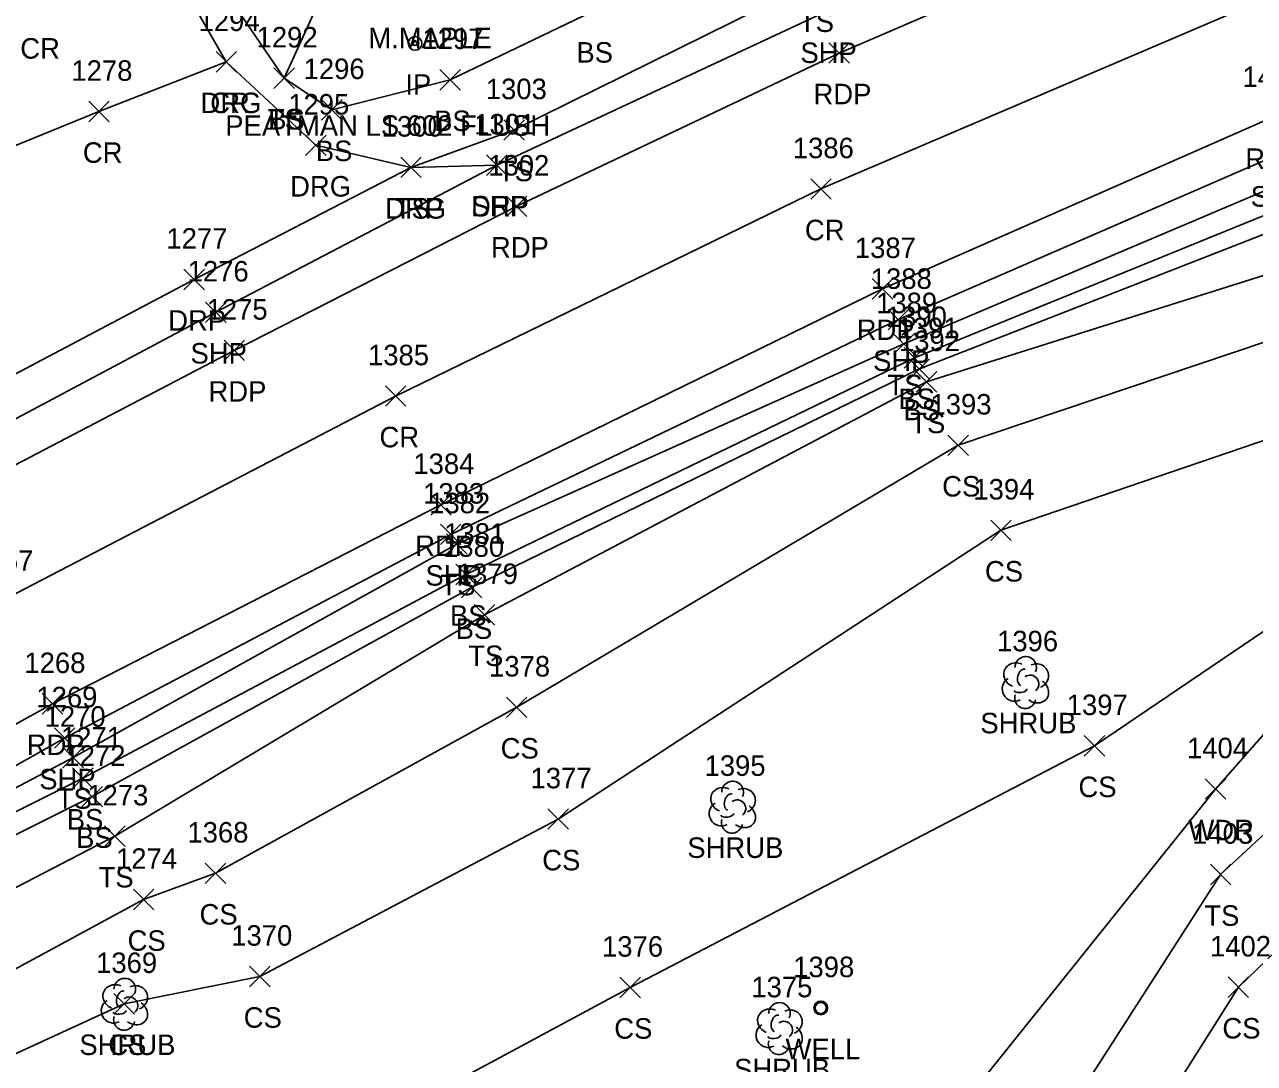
# Model space of a CAD drawing. Extents: x 1606530 to 1613020, y 784959 to 789666.
# Drawn here: x 1608940 to 1609059.8, y 788297.7 to 788399 of the extents above; entities that cross this region are included whole.
import ezdxf

# ---------------------------------------------------------------- set-up
doc = ezdxf.new("R2010")
doc.units = 0
for name, color, linetype in [('L_A', 7, 'Continuous'), ('L_C', 7, 'Continuous'), ('L_I', 7, 'Continuous'), ('L_TIC', 7, 'Continuous'), ('LAWA', 7, 'Continuous'), ('LELB', 7, 'Continuous'), ('LSH', 7, 'Continuous'), ('M_A', 7, 'Continuous'), ('M_C', 7, 'Continuous'), ('MPIR', 7, 'Continuous'), ('P_A', 7, 'Continuous'), ('P_I', 7, 'Continuous'), ('P_TIC', 7, 'Continuous'), ('PET', 7, 'Continuous'), ('PRC', 7, 'Continuous'), ('PSP', 7, 'Continuous'), ('R_A', 7, 'Continuous'), ('R_I', 7, 'Continuous'), ('R_TIC', 7, 'Continuous'), ('RDG', 7, 'Continuous'), ('RDP', 7, 'Continuous'), ('U_A', 7, 'Continuous'), ('U_I', 7, 'Continuous'), ('UWW', 7, 'Continuous')]:
    doc.layers.add(name, color=color, linetype=linetype)

msp = doc.modelspace()

# ---------------------------------------------------------------- linework, layer by layer
at = {"layer": 'L_TIC'}
for points in [[(1608964.26, 788392.75), (1608966.26, 788394.75)], [(1608966.26, 788392.75), (1608964.26, 788394.75)], [(1608964.26, 788392.75), (1608966.26, 788394.75)], [(1608966.26, 788392.75), (1608964.26, 788394.75)], [(1608980.43, 788392.6), (1608982.43, 788394.6)], [(1608982.43, 788392.6), (1608980.43, 788394.6)], [(1608968.9, 788389.67), (1608970.9, 788391.67)], [(1608970.9, 788389.67), (1608968.9, 788391.67)], [(1608986.68, 788387.71), (1608988.68, 788389.71)], [(1608988.68, 788387.71), (1608986.68, 788389.71)], [(1608976.62, 788384.06), (1608978.62, 788386.06)], [(1608978.62, 788384.06), (1608976.62, 788386.06)], [(1609024.65, 788366.84), (1609026.65, 788368.84)], [(1609026.65, 788366.84), (1609024.65, 788368.84)], [(1609025.68, 788365.49), (1609027.68, 788367.49)], [(1609027.68, 788365.49), (1609025.68, 788367.49)], [(1609026.17, 788364.4), (1609028.17, 788366.4)], [(1609028.17, 788364.4), (1609026.17, 788366.4)], [(1609026.87, 788363.14), (1609028.87, 788365.14)], [(1609028.87, 788363.14), (1609026.87, 788365.14)], [(1609029.95, 788356.96), (1609031.95, 788358.96)], [(1609031.95, 788356.96), (1609029.95, 788358.96)], [(1609034.12, 788348.67), (1609036.12, 788350.67)], [(1609036.12, 788348.67), (1609034.12, 788350.67)], [(1608981.09, 788347.33), (1608983.09, 788349.33)], [(1608983.09, 788347.33), (1608981.09, 788349.33)], [(1608981.98, 788344.36), (1608983.98, 788346.36)], [(1608983.98, 788344.36), (1608981.98, 788346.36)], [(1608982.53, 788343.08), (1608984.53, 788345.08)], [(1608984.53, 788343.08), (1608982.53, 788345.08)], [(1608983.79, 788340.43), (1608985.79, 788342.43)], [(1608985.79, 788340.43), (1608983.79, 788342.43)], [(1608986.92, 788331.41), (1608988.92, 788333.41)], [(1608988.92, 788331.41), (1608986.92, 788333.41)], [(1609043.23, 788327.65), (1609045.23, 788329.65)], [(1609045.23, 788327.65), (1609043.23, 788329.65)], [(1608943.69, 788326.51), (1608945.69, 788328.51)], [(1608945.69, 788326.51), (1608943.69, 788328.51)], [(1608944.63, 788324.49), (1608946.63, 788326.49)], [(1608946.63, 788324.49), (1608944.63, 788326.49)], [(1608945.54, 788322.7), (1608947.54, 788324.7)], [(1608947.54, 788322.7), (1608945.54, 788324.7)], [(1609055.03, 788323.44), (1609057.03, 788325.44)], [(1609057.03, 788323.44), (1609055.03, 788325.44)], [(1608990.96, 788320.51), (1608992.96, 788322.51)], [(1608992.96, 788320.51), (1608990.96, 788322.51)], [(1608947.76, 788318.84), (1608949.76, 788320.84)], [(1608949.76, 788318.84), (1608947.76, 788320.84)], [(1608957.57, 788315.22), (1608959.57, 788317.22)], [(1608959.57, 788315.22), (1608957.57, 788317.22)], [(1609055.53, 788315.1), (1609057.53, 788317.1)], [(1609057.53, 788315.1), (1609055.53, 788317.1)], [(1608950.56, 788312.66), (1608952.56, 788314.66)], [(1608952.56, 788312.66), (1608950.56, 788314.66)], [(1608961.88, 788305.16), (1608963.88, 788307.16)], [(1608963.88, 788305.16), (1608961.88, 788307.16)], [(1608997.99, 788304.09), (1608999.99, 788306.09)], [(1608999.99, 788304.09), (1608997.99, 788306.09)], [(1609057.26, 788304.11), (1609059.26, 788306.11)], [(1609059.26, 788304.11), (1609057.26, 788306.11)], [(1608948.67, 788302.5), (1608950.67, 788304.5)], [(1608950.67, 788302.5), (1608948.67, 788304.5)]]:
    msp.add_lwpolyline(points, dxfattribs=at)
at = {"layer": 'LAWA'}
msp.add_lwpolyline([(1609030.56, 788292.64), (1609056.03, 788324.44), (1609082.56, 788354.61), (1609090.16, 788369.42), (1609097.26, 788381.32), (1609109.23, 788386.03), (1609115.48, 788389.16), (1609124.65, 788392.27), (1609168.82, 788397.24), (1609199.02, 788403.22), (1609247.62, 788406.18), (1609289.08, 788410.02), (1609331.31, 788409.89), (1609380.07, 788411.97), (1609422.47, 788410.64), (1609441.9, 788412.64), (1609456.94, 788393.19), (1609459.97, 788389.84), (1609451.94, 788379.3), (1609445.61, 788371.6)], dxfattribs=at)
at = {"layer": 'LELB'}
for points in [[(1608946.18, 788421.74), (1608965.26, 788393.75), (1608969.9, 788390.67), (1608981.43, 788393.6), (1608995.3, 788400.27), (1609013.65, 788407.89), (1609037.32, 788417.63), (1609062.12, 788428.73), (1609080.77, 788438.94), (1609090.79, 788449.89)], [(1608970.54, 788442.59), (1608971.93, 788430.41), (1608970.74, 788414.31), (1608970.16, 788404.54), (1608965.26, 788393.75)], [(1608977.62, 788385.06), (1608987.68, 788388.71), (1609017.02, 788403.26), (1609039.26, 788411.43), (1609064.66, 788422.41), (1609086.61, 788432.67), (1609091.73, 788441.2)], [(1608830.7, 788263.06), (1608870.16, 788285.39), (1608903.61, 788303.66), (1608913.17, 788310.86), (1608944.69, 788327.51), (1608982.09, 788348.33), (1609025.65, 788367.84), (1609062.43, 788383.44), (1609080.36, 788388.45), (1609093.56, 788391.85), (1609111.49, 788398.34), (1609124.29, 788403.55), (1609165.33, 788413.89), (1609196.53, 788419.38), (1609241.91, 788424.94), (1609287.83, 788428.62), (1609331.16, 788428.8), (1609379, 788428.23), (1609424.69, 788425.72), (1609443.9, 788424.45), (1609475.84, 788418.57), (1609486.48, 788419.99), (1609502.63, 788421.7)], [(1608831.71, 788260.02), (1608870.92, 788283.54), (1608902.9, 788300.53), (1608905.17, 788302.06), (1608913.86, 788309.86), (1608916.94, 788311.14), (1608945.63, 788325.49), (1608982.98, 788345.36), (1609026.68, 788366.49), (1609062.42, 788381.05), (1609095.63, 788388.11), (1609108.11, 788392.39), (1609116.71, 788392.11), (1609124.65, 788392.27)], [(1608916.94, 788311.14), (1608917.75, 788309.33), (1608946.54, 788323.7), (1608983.53, 788344.08), (1609027.17, 788365.4), (1609062.77, 788379.31), (1609096.65, 788386.55), (1609108.63, 788390.01), (1609115.48, 788389.16)], [(1609044.69, 788283.6), (1609058.26, 788305.11), (1609096.98, 788342.47), (1609105.85, 788363.2), (1609115.48, 788389.16)], [(1609038.44, 788287.94), (1609056.53, 788316.1), (1609093.18, 788350), (1609102.91, 788366.58), (1609109.23, 788386.03)], [(1608913.17, 788310.86), (1608913.86, 788309.86), (1608915.93, 788307.4), (1608919.35, 788304.61), (1608948.76, 788319.84), (1608984.79, 788341.43), (1609027.87, 788364.14), (1609064.52, 788375.72), (1609081.68, 788376.85), (1609097.26, 788381.32)], [(1608906.35, 788297.69), (1608919.35, 788304.61), (1608926.6, 788300.13), (1608951.56, 788313.66), (1608958.57, 788316.22), (1608987.92, 788332.41), (1609030.95, 788357.96), (1609064.34, 788369.21), (1609081.68, 788376.85)], [(1608853.86, 788253.71), (1608879.11, 788266.69), (1608889.07, 788272.67), (1608908.34, 788283.28), (1608917.54, 788288.2), (1608929.97, 788294.46), (1608949.67, 788303.5), (1608962.88, 788306.16), (1608991.96, 788321.51), (1609035.12, 788349.67), (1609066.9, 788360.54), (1609090.16, 788369.42)], [(1608971.32, 788290.19), (1608998.99, 788305.09), (1609044.23, 788328.65), (1609082.56, 788354.61)]]:
    msp.add_lwpolyline(points, dxfattribs=at)
at = {"layer": 'LSH'}
for p, q in [((1609037.48, 788334.87), (1609037.48, 788334.87)), ((1609037.48, 788334.87), (1609037.48, 788334.87)), ((1609008.92, 788322.72), (1609008.92, 788322.72)), ((1609008.92, 788322.72), (1609008.92, 788322.72)), ((1608949.67, 788303.5), (1608949.67, 788303.5)), ((1608949.67, 788303.5), (1608949.67, 788303.5)), ((1609013.48, 788301.13), (1609013.48, 788301.13)), ((1609013.48, 788301.13), (1609013.48, 788301.13))]:
    msp.add_line(p, q, dxfattribs=at)
for centre in [(1609037.53, 788336.31), (1609008.97, 788324.15), (1608949.72, 788304.93), (1609013.53, 788302.56)]:
    msp.add_arc(centre, 1.05, 335.5272, 180.9563, dxfattribs=at)
for centre, major_axis, ratio, start_param, end_param in [((1609036.69, 788335.54), (1.21, -0.51), 0.895232, 1.570796, 4.712389), ((1609038.53, 788335.46), (-1.14, -0.48), 0.949671, 1.570796, 4.712389), ((1609036.4, 788334.17), (0.58, -1.04), 0.959034, 3.141593, 6.283185), ((1609037.28, 788335.33), (-0.208, -0.792), 0.645439, 3.141593, 6.283185), ((1609037.98, 788334.71), (-0.5, 0.667), 0.989748, 3.141593, 6.283185), ((1609037.03, 788334.12), (-0.625, -0.083), 0.423636, 0, 3.141593), ((1609038.49, 788334.04), (-1.09, 0.79), 0.841452, 1.570796, 4.712389), ((1609037.49, 788333.37), (0.26, 1.06), 0.942809, 1.570796, 4.712389), ((1609008.13, 788323.38), (1.21, -0.51), 0.895232, 1.570796, 4.712389), ((1609009.96, 788323.3), (-1.14, -0.48), 0.949671, 1.570796, 4.712389), ((1609008.71, 788323.17), (-0.208, -0.792), 0.645439, 3.141593, 6.283185), ((1609009.42, 788322.55), (-0.5, 0.667), 0.989748, 3.141593, 6.283185), ((1609007.84, 788322.01), (0.58, -1.04), 0.959034, 3.141593, 6.283185), ((1609008.46, 788321.97), (-0.625, -0.083), 0.423636, 0, 3.141593), ((1609009.92, 788321.88), (-1.09, 0.79), 0.841452, 1.570796, 4.712389), ((1609008.92, 788321.22), (0.26, 1.06), 0.942809, 1.570796, 4.712389), ((1608948.88, 788304.16), (1.21, -0.51), 0.895232, 1.570796, 4.712389), ((1608950.72, 788304.08), (-1.14, -0.48), 0.949671, 1.570796, 4.712389), ((1608949.47, 788303.95), (-0.208, -0.792), 0.645439, 3.141593, 6.283185), ((1608950.17, 788303.33), (-0.5, 0.667), 0.989748, 3.141593, 6.283185), ((1608948.59, 788302.79), (0.58, -1.04), 0.959034, 3.141593, 6.283185), ((1608950.67, 788302.66), (-1.09, 0.79), 0.841452, 1.570796, 4.712389), ((1609012.69, 788301.79), (1.21, -0.51), 0.895232, 1.570796, 4.712389), ((1609014.52, 788301.71), (-1.14, -0.48), 0.949671, 1.570796, 4.712389), ((1608949.67, 788302), (0.26, 1.06), 0.942809, 1.570796, 4.712389), ((1608949.22, 788302.75), (-0.625, -0.083), 0.423636, 0, 3.141593), ((1609013.27, 788301.59), (-0.208, -0.792), 0.645439, 3.141593, 6.283185), ((1609013.98, 788300.96), (-0.5, 0.667), 0.989748, 3.141593, 6.283185), ((1609012.4, 788300.42), (0.58, -1.04), 0.959034, 3.141593, 6.283185), ((1609013.02, 788300.38), (-0.625, -0.083), 0.423636, 0, 3.141593), ((1609014.48, 788300.3), (-1.09, 0.79), 0.841452, 1.570796, 4.712389), ((1609013.48, 788299.63), (0.26, 1.06), 0.942809, 1.570796, 4.712389)]:
    msp.add_ellipse(centre, major_axis=major_axis, ratio=ratio, start_param=start_param, end_param=end_param, dxfattribs=at)
at = {"layer": 'MPIR'}
msp.add_lwpolyline([(1608978.02, 788397.47), (1608977.74, 788396.97), (1608978.31, 788396.97)], close=True, dxfattribs=at)
msp.add_circle((1608978.02, 788397.14), 0.667, dxfattribs=at)
at = {"layer": 'P_TIC'}
for points in [[(1608958.62, 788394.35), (1608960.62, 788396.35)], [(1608960.62, 788394.35), (1608958.62, 788396.35)], [(1609018.36, 788395.21), (1609020.36, 788397.21)], [(1609020.36, 788395.21), (1609018.36, 788397.21)], [(1608946.21, 788389.5), (1608948.21, 788391.5)], [(1608948.21, 788389.5), (1608946.21, 788391.5)], [(1608984.98, 788384.27), (1608986.98, 788386.27)], [(1608986.98, 788384.27), (1608984.98, 788386.27)], [(1609016.58, 788381.95), (1609018.58, 788383.95)], [(1609018.58, 788381.95), (1609016.58, 788383.95)], [(1608986.92, 788380.26), (1608988.92, 788382.26)], [(1608988.92, 788380.26), (1608986.92, 788382.26)], [(1609022.57, 788372.22), (1609024.57, 788374.22)], [(1609024.57, 788372.22), (1609022.57, 788374.22)], [(1608957.6, 788369.93), (1608959.6, 788371.93)], [(1608959.6, 788369.93), (1608957.6, 788371.93)], [(1609024.12, 788369.21), (1609026.12, 788371.21)], [(1609026.12, 788369.21), (1609024.12, 788371.21)], [(1608959.4, 788366.21), (1608961.4, 788368.21)], [(1608961.4, 788366.21), (1608959.4, 788368.21)], [(1608975.12, 788361.76), (1608977.12, 788363.76)], [(1608977.12, 788361.76), (1608975.12, 788363.76)], [(1608979.54, 788351.16), (1608981.54, 788353.16)], [(1608981.54, 788351.16), (1608979.54, 788353.16)], [(1608980.49, 788348.27), (1608982.49, 788350.27)], [(1608982.49, 788348.27), (1608980.49, 788350.27)], [(1608941.68, 788331.75), (1608943.68, 788333.75)], [(1608943.68, 788331.75), (1608941.68, 788333.75)], [(1608942.86, 788328.41), (1608944.86, 788330.41)], [(1608944.86, 788328.41), (1608942.86, 788330.41)]]:
    msp.add_lwpolyline(points, dxfattribs=at)
at = {"layer": 'PET'}
for points in [[(1608827.2, 788266.24), (1608867.86, 788290.54), (1608906.68, 788312.86), (1608942.68, 788332.75), (1608980.54, 788352.16), (1609023.57, 788373.22), (1609061.44, 788389.9), (1609090.8, 788401.17), (1609121.92, 788410.09), (1609165.17, 788420), (1609195.85, 788425.54), (1609240.14, 788431.13), (1609287.88, 788434.37), (1609331.48, 788435.11), (1609378.89, 788434.05), (1609425.43, 788432.25), (1609443.83, 788431.33), (1609477.32, 788429.78), (1609518.44, 788427.6), (1609569.18, 788424.68), (1609602.99, 788422.58), (1609641.45, 788420.37), (1609681.7, 788417.92), (1609727.38, 788415.53)], [(1608858.1, 788310.73), (1608896.56, 788332.46), (1608932.58, 788352.68), (1608960.4, 788367.21), (1608987.92, 788381.26), (1609019.36, 788396.21), (1609040.55, 788405.36), (1609066.48, 788415.58), (1609102.05, 788427.76), (1609127.71, 788434.8)]]:
    msp.add_lwpolyline(points, dxfattribs=at)
at = {"layer": 'PRC'}
for points in [[(1608863.25, 788300.9), (1608901.81, 788322.6), (1608937.61, 788342.72), (1608976.12, 788362.76), (1609017.58, 788382.95), (1609062.58, 788402.24), (1609089.79, 788412.89), (1609118.81, 788421.44), (1609162.84, 788431.75), (1609194.15, 788437.36), (1609237.64, 788442.85), (1609286.9, 788446.16), (1609332.71, 788446.44), (1609379.39, 788445.34), (1609425.62, 788443.43), (1609445.83, 788442.47), (1609477.78, 788440.95), (1609519.76, 788438.85), (1609569.72, 788435.9), (1609601.73, 788434.31), (1609642.39, 788431.82), (1609682.03, 788429.15), (1609726.55, 788426.79)], [(1608931.56, 788384.13), (1608947.21, 788390.5), (1608959.62, 788395.35)]]:
    msp.add_lwpolyline(points, dxfattribs=at)
at = {"layer": 'PSP'}
for points in [[(1608855.39, 788314.11), (1608894.81, 788336.59), (1608931.25, 788356.38), (1608958.6, 788370.93), (1608985.98, 788385.27), (1609018.03, 788400.24), (1609039.03, 788409.71), (1609065.41, 788420.26), (1609085.95, 788428.61), (1609114.12, 788436.45)], [(1608830.36, 788265), (1608869.22, 788287.4), (1608908.59, 788309.54), (1608943.86, 788329.41), (1608981.49, 788349.27), (1609025.12, 788370.21), (1609061.92, 788386.23), (1609076.39, 788391.44), (1609089.96, 788397.16), (1609122.92, 788407.13), (1609165.71, 788417.03), (1609196.42, 788422.44), (1609241.31, 788428.68), (1609287.88, 788431.58), (1609331.2, 788431.67), (1609378.92, 788430.28), (1609425.01, 788428.31)]]:
    msp.add_lwpolyline(points, dxfattribs=at)
at = {"layer": 'R_TIC'}
for points in [[(1608958.62, 788394.35), (1608960.62, 788396.35)], [(1608960.62, 788394.35), (1608958.62, 788396.35)], [(1608967.35, 788386.21), (1608969.35, 788388.21)], [(1608969.35, 788386.21), (1608967.35, 788388.21)], [(1608976.62, 788384.06), (1608978.62, 788386.06)], [(1608978.62, 788384.06), (1608976.62, 788386.06)], [(1608976.62, 788384.06), (1608978.62, 788386.06)], [(1608978.62, 788384.06), (1608976.62, 788386.06)], [(1608984.98, 788384.27), (1608986.98, 788386.27)], [(1608986.98, 788384.27), (1608984.98, 788386.27)], [(1608955.48, 788373.13), (1608957.48, 788375.13)], [(1608957.48, 788373.13), (1608955.48, 788375.13)]]:
    msp.add_lwpolyline(points, dxfattribs=at)
at = {"layer": 'RDG'}
msp.add_lwpolyline([(1608946.18, 788421.74), (1608953.39, 788406.22), (1608959.62, 788395.35), (1608968.35, 788387.21), (1608977.62, 788385.06)], dxfattribs=at)
at = {"layer": 'RDP'}
msp.add_lwpolyline([(1608931.25, 788356.38), (1608933.71, 788362.09), (1608956.48, 788374.13), (1608977.62, 788385.06), (1608985.98, 788385.27)], dxfattribs=at)
at = {"layer": 'UWW'}
for radius in [0.667, 0.625, 0.583, 0.542]:
    msp.add_circle((1609017.56, 788303.09), radius, dxfattribs=at)

# ---------------------------------------------------------------- texts
at = {"layer": 'L_A'}
for s, p in [('TS', (1609015.43, 788398.26)), ('BS', (1608993.74, 788395.27)), ('TS', (1608963.67, 788388.75)), ('BS', (1608963.7, 788388.75)), ('BS', (1608979.87, 788388.6)), ('BS', (1608968.34, 788385.67)), ('TS', (1608986.09, 788383.71)), ('TS', (1608976.03, 788380.06)), ('TS', (1609024.06, 788362.84)), ('BS', (1609025.12, 788361.49)), ('BS', (1609025.61, 788360.4)), ('TS', (1609026.28, 788359.14)), ('CS', (1609029.39, 788352.96)), ('CS', (1609033.56, 788344.67)), ('TS', (1608980.5, 788343.33)), ('BS', (1608981.42, 788340.36)), ('BS', (1608981.97, 788339.08)), ('TS', (1608983.2, 788336.43)), ('SHRUB', (1609033.11, 788329.87)), ('CS', (1608986.36, 788327.41)), ('CS', (1609042.67, 788323.65)), ('TS', (1608943.1, 788322.51)), ('BS', (1608944.07, 788320.49)), ('WDR', (1609053.39, 788319.44)), ('BS', (1608944.98, 788318.7)), ('SHRUB', (1609004.55, 788317.72)), ('CS', (1608990.41, 788316.51)), ('TS', (1608947.17, 788314.84)), ('CS', (1608957.01, 788311.22)), ('TS', (1609054.94, 788311.1)), ('CS', (1608950, 788308.66)), ('CS', (1608961.32, 788301.16)), ('CS', (1608997.43, 788300.09)), ('CS', (1609056.7, 788300.11)), ('SHRUB', (1608945.3, 788298.5)), ('CS', (1608948.12, 788298.5)), ('SHRUB', (1609009.11, 788296.13))]:
    msp.add_text(s, height=2, dxfattribs=at).set_placement(p)
at = {"layer": 'L_C'}
msp.add_text('M.MAPLE', height=2, dxfattribs=at).set_placement((1608973.46, 788396.68))
at = {"layer": 'L_I'}
for s, p in [('1292', (1608962.57, 788396.75)), ('1292', (1608962.57, 788396.75)), ('1297', (1608978.73, 788396.6)), ('1296', (1608967.15, 788393.67)), ('1303', (1608984.91, 788391.71)), ('1300', (1608974.76, 788388.06)), ('1389', (1609022.95, 788370.84)), ('1390', (1609023.9, 788369.49)), ('1391', (1609025.04, 788368.4)), ('1392', (1609025.18, 788367.14)), ('1393', (1609028.25, 788360.96)), ('1394', (1609032.43, 788352.67)), ('1382', (1608979.39, 788351.33)), ('1381', (1608980.85, 788348.36)), ('1380', (1608980.75, 788347.08)), ('1379', (1608982.09, 788344.43)), ('1396', (1609034.74, 788337.87)), ('1378', (1608985.23, 788335.41)), ('1397', (1609041.53, 788331.65)), ('1270', (1608941.91, 788330.51)), ('1271', (1608943.5, 788328.49)), ('1404', (1609053.25, 788327.44)), ('1272', (1608943.84, 788326.7)), ('1395', (1609006.23, 788325.72)), ('1377', (1608989.27, 788324.51)), ('1273', (1608946.07, 788322.84)), ('1368', (1608955.83, 788319.22)), ('1403', (1609053.75, 788319.1)), ('1274', (1608948.87, 788316.66)), ('1370', (1608960.1, 788309.16)), ('1376', (1608996.24, 788308.09)), ('1402', (1609055.49, 788308.11)), ('1369', (1608946.93, 788306.5)), ('1369', (1608946.93, 788306.5)), ('1375', (1609010.79, 788304.13))]:
    msp.add_text(s, height=2, dxfattribs=at).set_placement(p)
at = {"layer": 'M_A'}
msp.add_text('IP', height=2, dxfattribs=at).set_placement((1608977.07, 788392.14))
at = {"layer": 'M_C'}
msp.add_text('PEATMAN LS 602 FLUSH', height=2, dxfattribs=at).set_placement((1608959.52, 788388.14))
at = {"layer": 'P_A'}
for s, p in [('CR', (1608939.54, 788395.66)), ('SHP', (1609015.57, 788395.24)), ('RDP', (1609016.85, 788391.21)), ('CR', (1608958.05, 788390.35)), ('CR', (1608945.64, 788385.5)), ('RDP', (1609058.93, 788384.9)), ('SHP', (1609059.46, 788381.23)), ('SHP', (1608983.52, 788380.27)), ('CR', (1609016.01, 788377.95)), ('RDP', (1608985.41, 788376.26)), ('RDP', (1609021.06, 788368.22)), ('SHP', (1608956.13, 788365.93)), ('SHP', (1609022.66, 788365.21)), ('RDP', (1608957.88, 788362.21)), ('CR', (1608974.55, 788357.76)), ('RDP', (1608978.03, 788347.16)), ('SHP', (1608979.03, 788344.27)), ('RDP', (1608940.17, 788327.75)), ('SHP', (1608941.39, 788324.41))]:
    msp.add_text(s, height=2, dxfattribs=at).set_placement(p)
at = {"layer": 'P_I'}
for s, p in [('1294', (1608956.92, 788398.35)), ('1278', (1608944.52, 788393.5)), ('1420', (1609058.66, 788392.9)), ('1301', (1608983.78, 788388.27)), ('1386', (1609014.83, 788385.95)), ('1302', (1608985.15, 788384.26)), ('1387', (1609020.88, 788376.22)), ('1276', (1608955.85, 788373.93)), ('1388', (1609022.43, 788373.21)), ('1275', (1608957.7, 788370.21)), ('1385', (1608973.43, 788365.76)), ('1384', (1608977.85, 788355.16)), ('1383', (1608978.8, 788352.27)), ('1267', (1608934.87, 788345.72)), ('1268', (1608939.94, 788335.75)), ('1269', (1608941.11, 788332.41))]:
    msp.add_text(s, height=2, dxfattribs=at).set_placement(p)
at = {"layer": 'R_A'}
for s, p in [('DRG', (1608957.1, 788390.35)), ('DRG', (1608965.84, 788382.21)), ('DRG', (1608975.11, 788380.06)), ('DRP', (1608975.11, 788380.06)), ('DRP', (1608983.47, 788380.27)), ('DRP', (1608953.96, 788369.13))]:
    msp.add_text(s, height=2, dxfattribs=at).set_placement(p)
at = {"layer": 'R_I'}
for s, p in [('1294', (1608956.92, 788398.35)), ('1295', (1608965.66, 788390.21)), ('1300', (1608974.76, 788388.06)), ('1300', (1608974.76, 788388.06)), ('1301', (1608983.78, 788388.27)), ('1277', (1608953.78, 788377.13))]:
    msp.add_text(s, height=2, dxfattribs=at).set_placement(p)
at = {"layer": 'U_A'}
msp.add_text('WELL', height=2, dxfattribs=at).set_placement((1609014.13, 788298.09))
at = {"layer": 'U_I'}
msp.add_text('1398', height=2, dxfattribs=at).set_placement((1609014.87, 788306.09))

doc.saveas('drawing.dxf')
